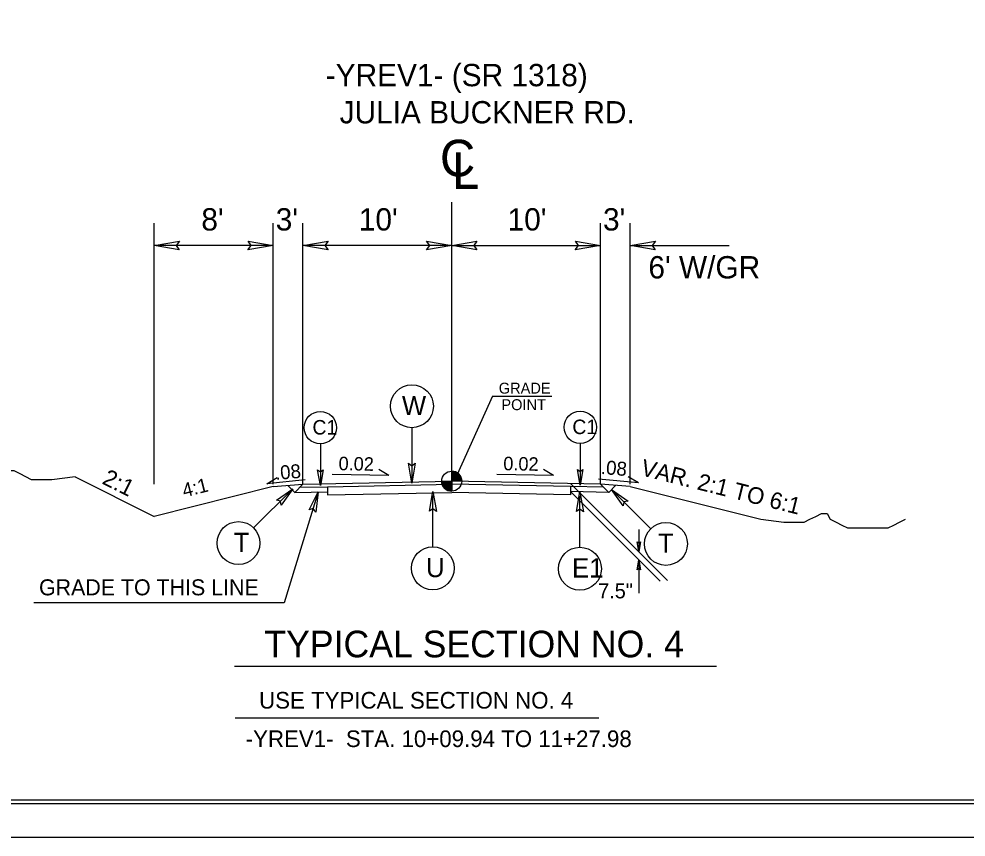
# Model space of a CAD drawing. Extents: x 1818040 to 1825768, y 638918 to 648046.
# Drawn here: x 1821432 to 1822069, y 644030 to 644580 of the extents above; entities that cross this region are included whole.
import ezdxf

# ---------------------------------------------------------------- set-up
doc = ezdxf.new("R2010")
doc.units = 0
for name, color, linetype in [('Old_Level_1', 7, 'Continuous'), ('Prop Dimension', 7, 'Continuous'), ('Prop Dimension Text', 7, 'Continuous'), ('Sheet Plot Border Inside CELL', 7, 'Continuous'), ('Sheet Plot Border Outside CELL', 7, 'Continuous'), ('Sheet Typical CELL', 7, 'Continuous'), ('Typical Grade Point Symbol CELL', 7, 'Continuous'), ('Typical ID Circle CELL', 7, 'Continuous'), ('Typical Pavement Slope CELL', 7, 'Continuous'), ('Typical Pavement Slope Information CELL', 7, 'Continuous'), ('Typical Shoulder Slope CELL', 7, 'Continuous'), ('Typical Slope Point Local CELL', 7, 'Continuous'), ('Typical Terminator CELL', 7, 'Continuous'), ('Typical Text Centerline CELL', 7, 'Continuous'), ('Typical Text General CELL', 7, 'Continuous'), ('Typical Text Grade Point CELL', 7, 'Continuous'), ('Typical Text ID Circle CELL', 7, 'Continuous'), ('Typical Text Label CELL', 7, 'Continuous')]:
    doc.layers.add(name, color=color, linetype=linetype)

msp = doc.modelspace()

# ---------------------------------------------------------------- linework, layer by layer
at = {"layer": 'Old_Level_1'}
for p, q in [((1821522.92, 644266.88), (1821522.92, 644442.33)), ((1821617.39, 644261.35), (1821612.72, 644266.03)), ((1821622.92, 644266.88), (1821617.39, 644261.35)), ((1821620.8, 644264.75), (1821639.4, 644265.13)), ((1821639.4, 644265.13), (1821722.92, 644266.8)), ((1821639.4, 644265.13), (1821639.4, 644259.7)), ((1821802.88, 644265.2), (1821722.92, 644266.8)), ((1821802.81, 644267.26), (1821867.97, 644202.1)), ((1821825.05, 644264.75), (1821802.88, 644265.2)), ((1821802.88, 644265.2), (1821802.88, 644259.77)), ((1821822.92, 644266.88), (1821828.45, 644261.35)), ((1821828.45, 644261.35), (1821833.13, 644266.03)), ((1821633.12, 644261.68), (1821610.33, 644187.14)), ((1821617.39, 644261.35), (1821639.4, 644261.79)), ((1821639.4, 644259.7), (1821722.92, 644261.37)), ((1821802.88, 644259.77), (1821722.92, 644261.37)), ((1821802.88, 644261.86), (1821863.01, 644201.74)), ((1821828.45, 644261.35), (1821802.88, 644261.86)), ((1821848.65, 644236.3), (1821848.65, 644221.47)), ((1821848.65, 644215.97), (1821848.65, 644193.65)), ((1821610.33, 644187.14), (1821441.92, 644187.14))]:
    msp.add_line(p, q, dxfattribs=at)
at = {"layer": 'Prop Dimension'}
for p, q in [((1821722.92, 644268.88), (1821722.92, 644456.54)), ((1821602.92, 644266.88), (1821602.92, 644442.33)), ((1821622.92, 644266.88), (1821622.92, 644442.33)), ((1821822.92, 644266.88), (1821822.92, 644442.33)), ((1821842.92, 644266.88), (1821842.92, 644442.33)), ((1821602.92, 644427.33), (1821522.92, 644427.33)), ((1821722.92, 644427.33), (1821622.92, 644427.33)), ((1821722.92, 644427.33), (1821822.92, 644427.33)), ((1821842.92, 644427.33), (1821909.46, 644427.33))]:
    msp.add_line(p, q, dxfattribs=at)
at = {"layer": 'Sheet Plot Border Inside CELL'}
msp.add_lwpolyline([(1822110.43, 645107.18), (1820443.93, 645107.18), (1820443.93, 644052.08), (1822110.43, 644052.08)], close=True, dxfattribs=at)
at = {"layer": 'Sheet Plot Border Outside CELL'}
msp.add_lwpolyline([(1822114.93, 645129.63), (1820430.93, 645129.63), (1820430.93, 644029.63), (1822114.93, 644029.63)], close=True, dxfattribs=at)
at = {"layer": 'Sheet Typical CELL'}
msp.add_line((1820430.93, 644029.63), (1822114.93, 644029.63), dxfattribs=at)
msp.add_lwpolyline([(1822097.93, 645104.63), (1820597.93, 645104.63), (1820597.93, 644054.63), (1822097.93, 644054.63)], close=True, dxfattribs=at)
at = {"layer": 'Typical Grade Point Symbol CELL'}
for p, q in [((1821722.92, 644268.88), (1821722.92, 644275.59)), ((1821716.21, 644268.88), (1821722.92, 644268.88)), ((1821722.91, 644262.17), (1821722.92, 644268.88)), ((1821722.92, 644268.88), (1821722.91, 644262.17)), ((1821729.64, 644268.88), (1821722.92, 644268.88))]:
    msp.add_line(p, q, dxfattribs=at)
for points in [[(1821722.98, 644275.59), (1821722.98, 644275.59), (1821722.98, 644268.88)], [(1821723.12, 644275.59), (1821723.12, 644268.88)], [(1821723.25, 644275.58), (1821723.25, 644268.88)], [(1821723.38, 644275.58), (1821723.38, 644268.88)], [(1821723.52, 644275.57), (1821723.52, 644268.88)], [(1821723.65, 644275.55), (1821723.65, 644268.88)], [(1821723.79, 644275.54), (1821723.79, 644268.88)], [(1821723.92, 644275.52), (1821723.92, 644268.88)], [(1821724.06, 644275.51), (1821724.06, 644268.88)], [(1821724.19, 644275.48), (1821724.19, 644268.88)], [(1821724.33, 644275.45), (1821724.33, 644268.88)], [(1821724.46, 644275.42), (1821724.46, 644268.88)], [(1821724.59, 644275.39), (1821724.59, 644268.88)], [(1821724.73, 644275.34), (1821724.73, 644268.88)], [(1821724.86, 644275.31), (1821724.86, 644268.88)], [(1821725, 644275.27), (1821725, 644268.88)], [(1821725.13, 644275.22), (1821725.13, 644268.88)], [(1821725.26, 644275.18), (1821725.26, 644268.88)], [(1821725.4, 644275.12), (1821725.4, 644268.88)], [(1821725.53, 644275.06), (1821725.53, 644268.88)], [(1821725.67, 644275), (1821725.67, 644268.88)], [(1821725.8, 644274.94), (1821725.8, 644268.88)], [(1821725.94, 644274.88), (1821725.94, 644268.88)], [(1821726.07, 644274.8), (1821726.07, 644268.88)], [(1821726.2, 644274.73), (1821726.2, 644268.88)], [(1821726.34, 644274.66), (1821726.34, 644268.88)], [(1821726.47, 644274.58), (1821726.47, 644268.88)], [(1821726.61, 644274.49), (1821726.61, 644268.88)], [(1821726.74, 644274.4), (1821726.74, 644268.88)], [(1821726.88, 644274.3), (1821726.88, 644268.88)], [(1821727.01, 644274.21), (1821727.01, 644268.88)], [(1821727.14, 644274.1), (1821727.14, 644268.88)], [(1821727.28, 644273.98), (1821727.28, 644268.88)], [(1821727.41, 644273.86), (1821727.41, 644268.88)], [(1821727.55, 644273.75), (1821727.55, 644268.88)], [(1821727.68, 644273.61), (1821727.68, 644268.88)], [(1821727.82, 644273.48), (1821727.82, 644268.88)], [(1821727.95, 644273.33), (1821727.95, 644268.88)], [(1821728.08, 644273.16), (1821728.08, 644268.88)], [(1821728.22, 644273), (1821728.22, 644268.88)], [(1821728.35, 644272.82), (1821728.35, 644268.88)], [(1821728.49, 644272.63), (1821728.49, 644268.88)], [(1821728.62, 644272.42), (1821728.62, 644268.88)], [(1821728.76, 644272.19), (1821728.76, 644268.88)], [(1821728.89, 644271.95), (1821728.89, 644268.88)], [(1821729.02, 644271.67), (1821729.02, 644268.88)], [(1821729.16, 644271.36), (1821729.16, 644268.88)], [(1821729.29, 644270.98), (1821729.29, 644268.88)], [(1821729.43, 644270.52), (1821729.43, 644268.88)], [(1821716.24, 644268.88), (1821716.24, 644268.15)], [(1821716.37, 644268.88), (1821716.37, 644267.36)], [(1821716.51, 644268.88), (1821716.51, 644266.88)], [(1821716.64, 644268.88), (1821716.64, 644266.48)], [(1821716.78, 644268.88), (1821716.78, 644266.17)], [(1821716.91, 644268.88), (1821716.91, 644265.88)], [(1821717.04, 644268.88), (1821717.04, 644265.63)], [(1821717.18, 644268.88), (1821717.18, 644265.39)], [(1821717.31, 644268.88), (1821717.31, 644265.18)], [(1821717.45, 644268.88), (1821717.45, 644264.99)], [(1821717.58, 644268.88), (1821717.58, 644264.81)], [(1821717.72, 644268.88), (1821717.72, 644264.64)], [(1821717.85, 644268.88), (1821717.85, 644264.48)], [(1821717.98, 644268.88), (1821717.98, 644264.33)], [(1821718.12, 644268.88), (1821718.12, 644264.18)], [(1821718.25, 644268.88), (1821718.25, 644264.05)], [(1821718.39, 644268.88), (1821718.39, 644263.93)], [(1821718.52, 644268.88), (1821718.52, 644263.81)], [(1821718.66, 644268.88), (1821718.66, 644263.69)], [(1821718.79, 644268.88), (1821718.79, 644263.58)], [(1821718.92, 644268.88), (1821718.92, 644263.48)], [(1821719.06, 644268.88), (1821719.06, 644263.39)], [(1821719.19, 644268.88), (1821719.19, 644263.3)], [(1821719.33, 644268.88), (1821719.33, 644263.21)], [(1821719.46, 644268.88), (1821719.46, 644263.12)], [(1821719.6, 644268.88), (1821719.6, 644263.05)], [(1821719.73, 644268.88), (1821719.73, 644262.97)], [(1821719.86, 644268.88), (1821719.86, 644262.9)], [(1821720, 644268.88), (1821720, 644262.84)], [(1821720.13, 644268.88), (1821720.13, 644262.78)], [(1821720.27, 644268.88), (1821720.27, 644262.72)], [(1821720.4, 644268.88), (1821720.4, 644262.66)], [(1821720.54, 644268.88), (1821720.54, 644262.6)], [(1821720.67, 644268.88), (1821720.67, 644262.56)], [(1821720.8, 644268.88), (1821720.8, 644262.51)], [(1821720.94, 644268.88), (1821720.94, 644262.47)], [(1821721.07, 644268.88), (1821721.07, 644262.44)], [(1821721.21, 644268.88), (1821721.21, 644262.39)], [(1821721.34, 644268.88), (1821721.34, 644262.36)], [(1821721.48, 644268.88), (1821721.48, 644262.33)], [(1821721.61, 644268.88), (1821721.61, 644262.3)], [(1821721.74, 644268.88), (1821721.74, 644262.27)], [(1821721.88, 644268.88), (1821721.88, 644262.26)], [(1821722.01, 644268.88), (1821722.01, 644262.23)], [(1821722.15, 644268.88), (1821722.15, 644262.21)], [(1821722.28, 644268.88), (1821722.28, 644262.2)], [(1821722.42, 644268.88), (1821722.42, 644262.18)], [(1821722.55, 644268.88), (1821722.55, 644262.18)], [(1821722.68, 644268.88), (1821722.68, 644262.17)], [(1821722.82, 644268.88), (1821722.82, 644262.17), (1821722.82, 644262.17)], [(1821729.56, 644269.84), (1821729.56, 644268.88)]]:
    msp.add_lwpolyline(points, dxfattribs=at)
msp.add_circle((1821722.91, 644268.88), 6.71, dxfattribs=at)
for start, end in [(359.99048, 89.99048), (179.99048, 269.99048)]:
    msp.add_arc((1821722.91, 644268.88), 6.71, start, end, dxfattribs=at)
at = {"layer": 'Typical ID Circle CELL'}
for p, q in [((1821696.16, 644304.85), (1821696.16, 644267.57)), ((1821634.61, 644293.97), (1821634.61, 644265.86)), ((1821809.33, 644294.25), (1821809.33, 644266.14)), ((1821589.76, 644237.47), (1821616.14, 644263.83)), ((1821710.22, 644224.72), (1821710.22, 644259.17)), ((1821809.12, 644224.46), (1821809.12, 644258.91)), ((1821856.71, 644236.93), (1821830.34, 644263.29))]:
    msp.add_line(p, q, dxfattribs=at)
for centre, radius in [((1821696.16, 644319.27), 14.43), ((1821634.61, 644304.85), 10.88), ((1821809.33, 644305.13), 10.88), ((1821579.57, 644227.26), 14.43), ((1821866.9, 644226.73), 14.43), ((1821710.22, 644210.3), 14.43), ((1821809.12, 644210.04), 14.43)]:
    msp.add_circle(centre, radius, dxfattribs=at)
at = {"layer": 'Typical Pavement Slope CELL'}
for p in [(1821622.92, 644266.88), (1821822.92, 644266.88)]:
    msp.add_line(p, (1821722.92, 644268.88), dxfattribs=at)
at = {"layer": 'Typical Pavement Slope Information CELL'}
for p, q in [((1821680.61, 644272.63), (1821673.86, 644276.71)), ((1821791.34, 644272.63), (1821784.58, 644276.71)), ((1821598.59, 644267.18), (1821605.49, 644271.35)), ((1821680.61, 644272.63), (1821642.64, 644273.39)), ((1821791.34, 644272.63), (1821753.36, 644273.39)), ((1821848.54, 644267.66), (1821821.67, 644270.25)), ((1821848.54, 644267.66), (1821841.65, 644271.82)), ((1821624.42, 644269.68), (1821598.59, 644267.18))]:
    msp.add_line(p, q, dxfattribs=at)
at = {"layer": 'Typical Shoulder Slope CELL'}
for p, q in [((1821602.92, 644265.22), (1821622.92, 644266.88)), ((1821842.92, 644265.22), (1821822.92, 644266.88))]:
    msp.add_line(p, q, dxfattribs=at)
at = {"layer": 'Typical Slope Point Local CELL'}
for p, q in [((1821469.72, 644271.81), (1821522.92, 644245.22)), ((1821602.92, 644265.22), (1821522.92, 644245.22)), ((1821842.92, 644265.22), (1821930.67, 644243.28))]:
    msp.add_line(p, q, dxfattribs=at)
for points in [[(1821469.72, 644271.81), (1821454.16, 644269.88), (1821450.27, 644269.88), (1821444.43, 644269.88), (1821440.54, 644269.88), (1821436.65, 644271.81), (1821432.76, 644273.77), (1821428.87, 644275.72), (1821424.98, 644275.72), (1821423.03, 644271.81), (1821419.14, 644269.88), (1821415.25, 644267.92), (1821411.36, 644265.99), (1821407.47, 644265.99), (1821403.58, 644265.99), (1821399.69, 644265.99), (1821395.8, 644265.99), (1821391.91, 644265.99)], [(1821930.67, 644243.28), (1821946.23, 644241.34), (1821950.12, 644241.34), (1821955.96, 644241.34), (1821959.85, 644241.34), (1821963.74, 644243.28), (1821967.63, 644245.23), (1821971.52, 644247.18), (1821975.41, 644247.18), (1821977.37, 644243.28), (1821981.26, 644241.34), (1821985.15, 644239.39), (1821989.04, 644237.45), (1821992.93, 644237.45), (1821996.82, 644237.45), (1822000.71, 644237.45), (1822004.6, 644237.45), (1822008.49, 644237.45), (1822012.38, 644237.45), (1822016.27, 644237.45), (1822020.16, 644239.39), (1822024.05, 644241.34), (1822027.94, 644243.28)]]:
    msp.add_lwpolyline(points, dxfattribs=at)
at = {"layer": 'Typical Terminator CELL'}
for points in [[(1821539.8, 644424.42), (1821522.92, 644427.33), (1821539.89, 644430.33), (1821537.73, 644427.33)], [(1821586.05, 644430.24), (1821602.92, 644427.33), (1821585.95, 644424.33), (1821588.11, 644427.33)], [(1821639.8, 644424.42), (1821622.92, 644427.33), (1821639.89, 644430.33), (1821637.73, 644427.33)], [(1821706.05, 644430.24), (1821722.92, 644427.33), (1821705.95, 644424.33), (1821708.11, 644427.33)], [(1821739.8, 644424.42), (1821722.92, 644427.33), (1821739.89, 644430.33), (1821737.73, 644427.33)], [(1821806.05, 644430.24), (1821822.92, 644427.33), (1821805.95, 644424.33), (1821808.11, 644427.33)], [(1821859.8, 644424.42), (1821842.92, 644427.33), (1821859.89, 644430.33), (1821857.73, 644427.33)], [(1821698.46, 644280.93), (1821696.16, 644267.57), (1821693.78, 644281), (1821696.16, 644279.29)], [(1821811.15, 644276.69), (1821809.33, 644266.14), (1821807.46, 644276.75), (1821809.33, 644275.4)], [(1821636.42, 644276.41), (1821634.61, 644265.86), (1821632.73, 644276.47), (1821634.61, 644275.12)], [(1821605.06, 644256.01), (1821616.14, 644263.83), (1821608.31, 644252.65), (1821607.84, 644255.54)], [(1821627.07, 644249.55), (1821633.13, 644261.67), (1821631.52, 644248.12), (1821629.74, 644250.44)], [(1821707.92, 644248.65), (1821710.22, 644262), (1821712.6, 644248.57), (1821710.22, 644250.28)], [(1821806.82, 644248.38), (1821809.12, 644261.74), (1821811.49, 644248.31), (1821809.12, 644250.01)], [(1821838.16, 644252.22), (1821830.34, 644263.29), (1821841.52, 644255.47), (1821838.63, 644255)], [(1821849.85, 644228.14), (1821848.65, 644221.47), (1821847.52, 644228.2), (1821848.7, 644227.33)], [(1821847.53, 644209.29), (1821848.65, 644215.97), (1821849.86, 644209.26), (1821848.67, 644210.11)]]:
    msp.add_lwpolyline(points, close=True, dxfattribs=at)
at = {"layer": 'Typical Text Grade Point CELL'}
for q in [(1821724.46, 644268.88), (1821790.23, 644325.98)]:
    msp.add_line((1821750.43, 644325.98), q, dxfattribs=at)
at = {"layer": 'Typical Text Label CELL'}
for p, q in [((1821576.92, 644144.47), (1821900.99, 644144.47)), ((1821577.31, 644109.85), (1821821.72, 644109.85))]:
    msp.add_line(p, q, dxfattribs=at)

# ---------------------------------------------------------------- texts
at = {"layer": 'Prop Dimension Text'}
for s, height, p in [('-YREV1- (SR 1318)', 15, (1821638.24, 644534.37)), ('JULIA BUCKNER RD.', 15, (1821647.57, 644509.4)), ("8'", 15, (1821554.61, 644437.39)), ("3'", 15, (1821604.61, 644437.39)), ("10'", 15, (1821660.48, 644437.39)), ("10'", 15, (1821760.48, 644437.39)), ("3'", 15, (1821824.61, 644437.39)), ("6' W/GR", 15, (1821855.14, 644405.18)), ('7.5"', 10, (1821821.34, 644190.12))]:
    msp.add_text(s, height=height, dxfattribs=at).set_placement(p)
at = {"layer": 'Typical Pavement Slope Information CELL'}
for p in [(1821646.8, 644276.26), (1821757.53, 644276.26)]:
    msp.add_text('0.02 ', height=9.107, rotation=358.85426, dxfattribs=at).set_placement(p)
at = {"layer": 'Typical Slope Point Local CELL'}
for s, rotation, p in [('.08', 4.76147, (1821604.52, 644269.68)), ('.08', 355.23853, (1821822.93, 644273.76)), ('4:1', 14.03624, (1821543.08, 644257.91))]:
    msp.add_text(s, height=9.373, rotation=rotation, dxfattribs=at).set_placement(p)
at = {"layer": 'Typical Text Centerline CELL'}
msp.add_text('C', height=24.6, dxfattribs=at).set_placement((1821714.99, 644473.8))
msp.add_text('L', height=24.62, rotation=359.9469, dxfattribs=at).set_placement((1821723.17, 644465.4))
at = {"layer": 'Typical Text General CELL'}
for s, height, rotation, p in [('VAR. 2:1 TO 6:1', 11.1896, 345.96376, (1821849.36, 644272.93)), ('2:1 ', 11.19, 333.43495, (1821487.25, 644267.47))]:
    msp.add_text(s, height=height, rotation=rotation, dxfattribs=at).set_placement(p)
msp.add_text('GRADE TO THIS LINE', height=10.742, dxfattribs=at).set_placement((1821445.5, 644192.14))
at = {"layer": 'Typical Text Grade Point CELL'}
for s, height, p in [('GRADE', 7.34, (1821754.53, 644327.74)), ('POINT', 7.34, (1821756.29, 644316.62)), ('-YREV1-  STA. 10+09.94 TO 11+27.98 ', 11.1896, (1821584.43, 644090.13))]:
    msp.add_text(s, height=height, dxfattribs=at).set_placement(p)
at = {"layer": 'Typical Text ID Circle CELL'}
for s, height, p in [('W', 12.91, (1821689.44, 644313.33)), ('C1', 9.735, (1821629.31, 644300.25)), ('C1', 9.735, (1821804.03, 644300.53)), ('T', 12.91, (1821576.36, 644221.32)), ('T', 12.91, (1821861.62, 644220.78)), ('U', 12.91, (1821705.66, 644204.36)), ('E1', 12.912, (1821803.79, 644204.09))]:
    msp.add_text(s, height=height, dxfattribs=at).set_placement(p)
at = {"layer": 'Typical Text Label CELL'}
for s, height, p in [('TYPICAL SECTION NO. 4', 17.9034, (1821596.96, 644150.46)), ('USE TYPICAL SECTION NO. 4', 11.1896, (1821593.42, 644115.99))]:
    msp.add_text(s, height=height, dxfattribs=at).set_placement(p)

doc.saveas('drawing.dxf')
